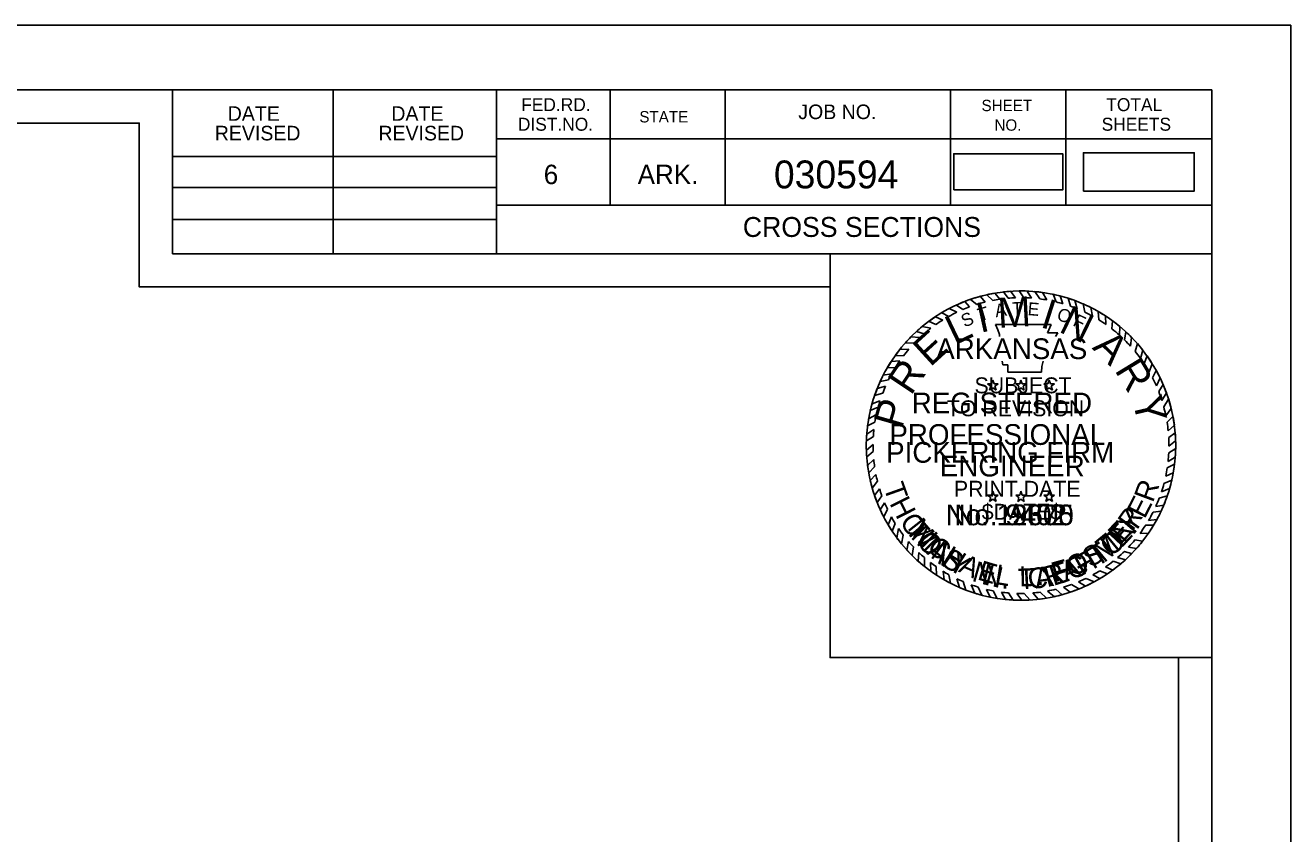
# Model space of a CAD drawing. Extents: x 1368713 to 1370673, y 380279 to 380950.
# Drawn here: x 1370239 to 1370315.2, y 380688.4 to 380737.1 of the extents above; entities that cross this region are included whole.
import ezdxf

# ---------------------------------------------------------------- set-up
doc = ezdxf.new("R2010")
doc.units = 0
for name, color, linetype in [('R_Border', 7, 'Continuous'), ('R_Border Notes', 7, 'Continuous'), ('R_No Plot', 7, 'Continuous'), ('R_Water', 7, 'Continuous'), ('STAMP_PE_CRAFTON', 7, 'Continuous'), ('STAMP_PE_FOSTER', 7, 'Continuous'), ('STAMP_PE_SEAL-INFO', 7, 'Continuous'), ('STAMP_PE_TAEGTMEYER', 7, 'Continuous'), ('STAMP_PE_TXT', 7, 'Continuous'), ('STAMP_PRELIMINARY', 7, 'Continuous')]:
    doc.layers.add(name, color=color, linetype=linetype)

msp = doc.modelspace()

# ---------------------------------------------------------------- linework, layer by layer
at = {"layer": 'R_Border'}
for p, q in [((1369994.283, 380733.214), (1370310.463, 380733.214)), ((1370247.823, 380723.334), (1370247.823, 380733.214)), ((1370257.503, 380723.334), (1370257.503, 380733.214)), ((1370267.363, 380733.214), (1370267.363, 380723.334)), ((1370274.203, 380733.214), (1370274.203, 380726.274)), ((1370281.143, 380733.214), (1370281.143, 380726.274)), ((1370294.723, 380733.214), (1370294.723, 380726.274)), ((1370301.663, 380733.214), (1370301.663, 380726.274)), ((1370310.463, 380527.754), (1370310.463, 380733.214)), ((1370310.463, 380730.274), (1370267.363, 380730.274)), ((1370310.463, 380730.294), (1370310.463, 380730.294)), ((1370247.823, 380729.194), (1370267.363, 380729.194)), ((1370247.823, 380727.334), (1370267.363, 380727.334)), ((1370310.463, 380726.274), (1370267.363, 380726.274)), ((1370270.323, 380726.274), (1370310.463, 380726.274)), ((1370247.823, 380725.394), (1370267.363, 380725.394)), ((1370310.463, 380723.334), (1370247.823, 380723.334))]:
    msp.add_line(p, q, dxfattribs=at)
at = {"layer": 'R_No Plot'}
for points in [[(1369981.875, 380737.108), (1370315.215, 380737.108), (1370315.215, 380523.771), (1369981.875, 380523.771)], [(1370308.463, 380632.484), (1369996.283, 380632.484), (1369996.283, 380731.214), (1370245.823, 380731.214), (1370245.823, 380721.334), (1370263.363, 380721.334), (1370287.463, 380721.334), (1370287.463, 380699.001), (1370308.463, 380699.001)], [(1369996.283, 380731.214), (1370245.823, 380731.214), (1370245.823, 380721.334), (1370263.363, 380721.334), (1370287.463, 380721.334), (1370287.463, 380699.001), (1370308.463, 380699.001), (1370308.463, 380529.754), (1369996.283, 380529.754)], [(1370287.463, 380723.334), (1370310.463, 380723.334), (1370310.463, 380699.001), (1370287.463, 380699.001)]]:
    msp.add_lwpolyline(points, close=True, dxfattribs=at)
at = {"layer": 'R_Water'}
for points in [[(1370302.721, 380727.118), (1370309.404, 380727.118), (1370309.404, 380729.429), (1370302.721, 380729.429)], [(1370294.911, 380727.181), (1370301.474, 380727.181), (1370301.474, 380729.367), (1370294.911, 380729.367)]]:
    msp.add_lwpolyline(points, close=True, dxfattribs=at)
at = {"layer": 'STAMP_PE_SEAL-INFO'}
for p, q in [((1370297.899, 380721.038), (1370298.18, 380720.655)), ((1370298.634, 380720.684), (1370298.322, 380721.077)), ((1370299.132, 380720.688), (1370298.854, 380721.098)), ((1370299.59, 380720.668), (1370299.332, 380721.092)), ((1370300.096, 380720.617), (1370299.804, 380721.061)), ((1370300.522, 380720.552), (1370300.264, 380721.008)), ((1370295.067, 380720.246), (1370295.456, 380719.971)), ((1370295.574, 380720.461), (1370295.869, 380720.136)), ((1370295.922, 380720.589), (1370296.303, 380720.284)), ((1370296.513, 380720.771), (1370296.801, 380720.424)), ((1370296.901, 380720.868), (1370297.257, 380720.525)), ((1370297.383, 380720.964), (1370297.682, 380720.597)), ((1370301.084, 380720.434), (1370300.91, 380720.893)), ((1370301.486, 380720.325), (1370301.326, 380720.794)), ((1370301.937, 380720.179), (1370301.796, 380720.658)), ((1370302.356, 380720.019), (1370302.211, 380720.515)), ((1370302.817, 380719.813), (1370302.714, 380720.311)), ((1370293.801, 380719.539), (1370294.243, 380719.337)), ((1370294.188, 380719.783), (1370294.62, 380719.56)), ((1370294.636, 380720.034), (1370295.099, 380719.809)), ((1370303.263, 380719.584), (1370303.176, 380720.093)), ((1370303.65, 380719.357), (1370303.611, 380719.858)), ((1370304.085, 380719.071), (1370304.054, 380719.586)), ((1370293.004, 380718.946), (1370293.533, 380718.845)), ((1370293.38, 380719.273), (1370293.836, 380719.068)), ((1370297.436, 380719.068), (1370300.78, 380719.068)), ((1370297.557, 380718.76), (1370297.436, 380719.068)), ((1370297.661, 380718.462), (1370297.557, 380718.76)), ((1370300.78, 380719.068), (1370300.555, 380718.576)), ((1370304.446, 380718.804), (1370304.48, 380719.291)), ((1370304.892, 380718.432), (1370304.912, 380718.954)), ((1370292.002, 380717.978), (1370292.523, 380717.939)), ((1370292.324, 380718.322), (1370292.869, 380718.281)), ((1370292.66, 380718.645), (1370293.119, 380718.507)), ((1370297.668, 380718.348), (1370297.661, 380718.462)), ((1370300.555, 380718.576), (1370301.187, 380718.576)), ((1370301.187, 380718.576), (1370301.042, 380718.348)), ((1370305.205, 380718.139), (1370305.274, 380718.638)), ((1370305.564, 380717.766), (1370305.63, 380718.292)), ((1370291.378, 380717.197), (1370291.883, 380717.192)), ((1370291.656, 380717.566), (1370292.205, 380717.589)), ((1370305.837, 380717.45), (1370305.974, 380717.921)), ((1370306.161, 380717.032), (1370306.297, 380717.532)), ((1370306.381, 380716.717), (1370306.559, 380717.181)), ((1370290.897, 380716.452), (1370291.386, 380716.472)), ((1370291.143, 380716.853), (1370291.659, 380716.886)), ((1370297.859, 380716.639), (1370297.833, 380716.857)), ((1370298.174, 380716.639), (1370297.859, 380716.639)), ((1370298.174, 380716.209), (1370298.174, 380716.639)), ((1370300.219, 380716.547), (1370300.203, 380716.209)), ((1370300.297, 380716.857), (1370300.219, 380716.547)), ((1370306.689, 380716.22), (1370306.872, 380716.711)), ((1370290.478, 380715.639), (1370290.981, 380715.743)), ((1370290.666, 380716.028), (1370291.164, 380716.093)), ((1370300.203, 380716.209), (1370298.174, 380716.209)), ((1370306.889, 380715.853), (1370307.115, 380716.298)), ((1370307.12, 380715.369), (1370307.346, 380715.854)), ((1370290.144, 380714.801), (1370290.628, 380714.937)), ((1370290.294, 380715.207), (1370290.798, 380715.353)), ((1370307.26, 380715.032), (1370307.524, 380715.466)), ((1370307.455, 380714.483), (1370307.726, 380714.958)), ((1370289.987, 380714.298), (1370290.465, 380714.466)), ((1370307.563, 380714.119), (1370307.857, 380714.571)), ((1370290.247, 380713.644), (1370289.782, 380713.395)), ((1370289.883, 380713.89), (1370290.353, 380714.083)), ((1370307.696, 380713.56), (1370308.015, 380714.007)), ((1370307.765, 380713.18), (1370308.118, 380713.533)), ((1370290.102, 380712.75), (1370289.666, 380712.469)), ((1370290.161, 380713.185), (1370289.716, 380712.963)), ((1370307.831, 380712.671), (1370308.204, 380713.007)), ((1370290.066, 380712.324), (1370289.645, 380712.068)), ((1370307.863, 380712.253), (1370308.254, 380712.544)), ((1370307.876, 380711.735), (1370308.281, 380712.056)), ((1370290.049, 380711.831), (1370289.644, 380711.496)), ((1370290.056, 380711.424), (1370289.665, 380711.099)), ((1370307.825, 380710.823), (1370308.259, 380711.08)), ((1370307.865, 380711.329), (1370308.284, 380711.606)), ((1370290.089, 380710.929), (1370289.718, 380710.572)), ((1370290.141, 380710.5), (1370289.787, 380710.126)), ((1370307.775, 380710.435), (1370308.218, 380710.654)), ((1370290.22, 380710.041), (1370289.88, 380709.673)), ((1370290.313, 380709.622), (1370290.001, 380709.207)), ((1370307.576, 380709.483), (1370308.048, 380709.685)), ((1370307.684, 380709.935), (1370308.139, 380710.13)), ((1370290.437, 380709.175), (1370290.142, 380708.757)), ((1370307.429, 380708.989), (1370307.919, 380709.19)), ((1370290.578, 380708.752), (1370290.296, 380708.34)), ((1370290.744, 380708.325), (1370290.483, 380707.903)), ((1370307.08, 380708.095), (1370307.568, 380708.191)), ((1370307.294, 380708.609), (1370307.777, 380708.74)), ((1370290.916, 380707.942), (1370290.688, 380707.481)), ((1370291.151, 380707.484), (1370290.96, 380706.994)), ((1370306.647, 380707.26), (1370307.148, 380707.314)), ((1370306.919, 380707.758), (1370307.407, 380707.826)), ((1370291.387, 380707.08), (1370291.203, 380706.609)), ((1370291.589, 380706.768), (1370291.479, 380706.216)), ((1370306.475, 380706.979), (1370306.953, 380706.973)), ((1370291.87, 380706.378), (1370291.768, 380705.847)), ((1370292.174, 380706), (1370292.087, 380705.48)), ((1370305.828, 380706.091), (1370306.289, 380706.012)), ((1370306.136, 380706.485), (1370306.64, 380706.488)), ((1370292.476, 380705.663), (1370292.414, 380705.14)), ((1370292.799, 380705.337), (1370292.769, 380704.808)), ((1370293.143, 380705.025), (1370293.14, 380704.496)), ((1370304.784, 380705.026), (1370305.255, 380704.897)), ((1370305.19, 380705.399), (1370305.631, 380705.261)), ((1370305.445, 380705.658), (1370305.922, 380705.573)), ((1370293.503, 380704.73), (1370293.522, 380704.206)), ((1370293.842, 380704.481), (1370293.878, 380703.962)), ((1370303.709, 380704.231), (1370304.158, 380704.036)), ((1370304.053, 380704.459), (1370304.491, 380704.27)), ((1370304.513, 380704.802), (1370304.981, 380704.656)), ((1370294.269, 380704.199), (1370294.329, 380703.686)), ((1370294.619, 380703.993), (1370294.71, 380703.48)), ((1370295.1, 380703.743), (1370295.257, 380703.222)), ((1370295.473, 380703.574), (1370295.645, 380703.064)), ((1370302.427, 380703.564), (1370302.851, 380703.303)), ((1370302.887, 380703.773), (1370303.37, 380703.561)), ((1370303.294, 380703.986), (1370303.711, 380703.754)), ((1370295.965, 380703.382), (1370296.174, 380702.88)), ((1370296.375, 380703.247), (1370296.601, 380702.758)), ((1370296.883, 380703.109), (1370297.095, 380702.643)), ((1370297.28, 380703.023), (1370297.527, 380702.565)), ((1370297.78, 380702.941), (1370298.02, 380702.501)), ((1370298.217, 380702.894), (1370298.491, 380702.465)), ((1370298.702, 380702.867), (1370299.004, 380702.454)), ((1370299.161, 380702.865), (1370299.505, 380702.469)), ((1370299.68, 380702.892), (1370300.006, 380702.512)), ((1370300.118, 380702.938), (1370300.491, 380702.58)), ((1370300.563, 380703.008), (1370300.952, 380702.668)), ((1370301.056, 380703.112), (1370301.434, 380702.787)), ((1370301.515, 380703.236), (1370301.932, 380702.939)), ((1370302.008, 380703.399), (1370302.451, 380703.131))]:
    msp.add_line(p, q, dxfattribs=at)
for radius, start, end in [(9.323, 93.93815, 96.55172), (9.323, 87.72979, 90.67067), (9.323, 81.97315, 84.82355), (9.323, 111.31242, 114.70259), (9.323, 105.23389, 109.03519), (8.914, 104.03521, 107.36155), (9.323, 99.75254, 102.77648), (8.914, 98.25799, 101.03289), (8.914, 92.11016, 95.03666), (8.914, 85.96279, 88.9097), (8.914, 79.92642, 82.69597), (9.323, 75.31251, 77.94263), (8.914, 73.55748, 76.23144), (9.323, 69.60611, 72.30577), (9.323, 63.13288, 66.2704), (9.323, 123.61993, 126.59063), (9.323, 117.65441, 120.80988), (8.914, 115.68692, 119.15827), (8.914, 110.30864, 113.16588), (8.914, 67.62483, 70.50398), (8.914, 61.15575, 64.37837), (9.323, 56.90029, 60.09423), (9.323, 129.73259, 132.53764), (8.914, 127.52969, 130.96829), (8.914, 121.97456, 125.11001), (8.914, 54.92383, 58.27016), (8.914, 48.30163, 52.03953), (9.323, 50.3492, 53.71593), (9.323, 135.40208, 138.30314), (8.914, 133.13306, 136.25623), (8.914, 42.22116, 45.55119), (9.323, 44.3405, 47.39292), (9.323, 141.60556, 144.44865), (8.914, 139.30101, 142.58729), (8.914, 36.13503, 39.53106), (9.323, 38.12472, 41.23157), (9.323, 31.96138, 35.42937), (9.323, 147.00719, 149.89904), (8.914, 145.01972, 148.21036), (8.914, 29.90321, 33.66454), (9.323, 152.86398, 155.51889), (8.914, 151.03153, 153.57304), (8.914, 23.77322, 27.22114), (9.323, 25.93909, 29.01247), (9.323, 158.40766, 161.07015), (8.914, 156.34018, 159.23194), (8.914, 17.68022, 21.42509), (9.323, 19.95381, 23.31409), (9.323, 164.3068, 166.89395), (8.914, 162.43309, 165.00133), (9.323, 13.84205, 17.44468), (9.323, 170.0003, 172.68778), (8.914, 167.90481, 170.90393), (8.914, 11.54445, 15.23639), (9.323, 7.58519, 10.86211), (8.914, 173.73, 176.47337), (8.914, 5.7599, 9.06056), (9.323, 175.74093, 178.2066), (8.914, 359.73289, 3.06392), (9.323, 1.72155, 4.72681), (9.323, 181.72508, 184.16255), (8.914, 179.64537, 182.26333), (8.914, 353.86319, 357.12742), (9.323, 355.71562, 358.95694), (9.323, 187.42037, 190.19271), (8.914, 185.45389, 188.23401), (8.914, 348.07782, 351.34355), (9.323, 349.83047, 353.08845), (9.323, 193.03695, 195.99732), (8.914, 191.22736, 193.98583), (9.323, 343.89247, 347.03502), (8.914, 196.96751, 199.83526), (8.914, 341.77699, 345.09248), (9.323, 198.89671, 201.62812), (8.914, 202.77613, 205.47915), (8.914, 335.6038, 339.18578), (9.323, 337.38367, 340.99332), (9.323, 204.54793, 207.43282), (8.914, 208.78826, 211.79343), (8.914, 329.55488, 333.20757), (9.323, 331.40371, 334.93315), (9.323, 210.86355, 213.65709), (8.914, 214.18375, 217.27474), (8.914, 323.58513, 327.44069), (9.323, 325.44052, 328.98725), (9.323, 216.61154, 219.49098), (8.914, 220.39088, 223.30564), (8.914, 316.65308, 320.37109), (9.323, 318.28455, 321.80429), (9.323, 222.47995, 225.38008), (8.914, 226.24938, 229.24068), (8.914, 310.77436, 314.31605), (9.323, 312.45177, 315.66328), (9.323, 228.36648, 231.34802), (8.914, 232.22904, 234.93361), (8.914, 299.07679, 302.17235), (8.914, 304.82299, 308.51428), (9.323, 306.37206, 310.20799), (9.323, 234.29502, 236.94517), (8.914, 238.22227, 240.83529), (9.323, 240.1977, 242.86128), (8.914, 244.32043, 246.94859), (8.914, 292.87452, 296.11851), (9.323, 294.64808, 298.21662), (9.323, 300.62101, 303.87026), (9.323, 246.57598, 249.15579), (8.914, 250.34912, 253.12157), (9.323, 252.59667, 255.32518), (8.914, 256.50505, 259.11916), (8.914, 262.37828, 265.20115), (8.914, 268.3215, 271.27698), (8.914, 274.61565, 277.44863), (8.914, 280.34588, 283.58137), (9.323, 282.31994, 285.37019), (8.914, 286.64233, 289.97826), (9.323, 288.57086, 291.97334), (9.323, 258.44328, 261.13983), (9.323, 264.19784, 267.10092), (9.323, 270.25484, 273.33609), (9.323, 276.42389, 279.43574)]:
    msp.add_arc((1370298.963, 380711.776), radius, start, end, dxfattribs=at)
at = {"layer": 'STAMP_PE_TXT'}
for p, q in [((1370297.189, 380715.492), (1370297.265, 380715.725)), ((1370297.265, 380715.725), (1370297.34, 380715.492)), ((1370298.887, 380715.492), (1370298.963, 380715.725)), ((1370298.963, 380715.725), (1370299.038, 380715.492)), ((1370300.585, 380715.492), (1370300.661, 380715.725)), ((1370300.661, 380715.725), (1370300.736, 380715.492)), ((1370297.142, 380715.348), (1370296.944, 380715.492)), ((1370296.944, 380715.492), (1370297.189, 380715.492)), ((1370297.066, 380715.114), (1370297.142, 380715.348)), ((1370297.265, 380715.259), (1370297.066, 380715.114)), ((1370297.463, 380715.114), (1370297.265, 380715.259)), ((1370297.34, 380715.492), (1370297.586, 380715.492)), ((1370297.586, 380715.492), (1370297.387, 380715.348)), ((1370297.387, 380715.348), (1370297.463, 380715.114)), ((1370298.84, 380715.348), (1370298.642, 380715.492)), ((1370298.642, 380715.492), (1370298.887, 380715.492)), ((1370298.764, 380715.114), (1370298.84, 380715.348)), ((1370298.963, 380715.259), (1370298.764, 380715.114)), ((1370299.161, 380715.114), (1370298.963, 380715.259)), ((1370299.038, 380715.492), (1370299.284, 380715.492)), ((1370299.284, 380715.492), (1370299.085, 380715.348)), ((1370299.085, 380715.348), (1370299.161, 380715.114)), ((1370300.538, 380715.348), (1370300.34, 380715.492)), ((1370300.34, 380715.492), (1370300.585, 380715.492)), ((1370300.462, 380715.114), (1370300.538, 380715.348)), ((1370300.661, 380715.259), (1370300.462, 380715.114)), ((1370300.859, 380715.114), (1370300.661, 380715.259)), ((1370300.736, 380715.492), (1370300.982, 380715.492)), ((1370300.982, 380715.492), (1370300.783, 380715.348)), ((1370300.783, 380715.348), (1370300.859, 380715.114)), ((1370297.142, 380708.641), (1370296.944, 380708.785)), ((1370296.944, 380708.785), (1370297.189, 380708.785)), ((1370297.189, 380708.785), (1370297.265, 380709.018)), ((1370297.265, 380709.018), (1370297.34, 380708.785)), ((1370297.34, 380708.785), (1370297.586, 380708.785)), ((1370297.586, 380708.785), (1370297.387, 380708.641)), ((1370298.84, 380708.641), (1370298.642, 380708.785)), ((1370298.642, 380708.785), (1370298.887, 380708.785)), ((1370298.887, 380708.785), (1370298.963, 380709.018)), ((1370298.963, 380709.018), (1370299.038, 380708.785)), ((1370299.038, 380708.785), (1370299.284, 380708.785)), ((1370299.284, 380708.785), (1370299.085, 380708.641)), ((1370300.538, 380708.641), (1370300.34, 380708.785)), ((1370300.34, 380708.785), (1370300.585, 380708.785)), ((1370300.585, 380708.785), (1370300.661, 380709.018)), ((1370300.661, 380709.018), (1370300.736, 380708.785)), ((1370300.736, 380708.785), (1370300.982, 380708.785)), ((1370300.982, 380708.785), (1370300.783, 380708.641)), ((1370297.066, 380708.407), (1370297.142, 380708.641)), ((1370297.265, 380708.552), (1370297.066, 380708.407)), ((1370297.463, 380708.407), (1370297.265, 380708.552)), ((1370297.387, 380708.641), (1370297.463, 380708.407)), ((1370298.764, 380708.407), (1370298.84, 380708.641)), ((1370298.963, 380708.552), (1370298.764, 380708.407)), ((1370299.161, 380708.407), (1370298.963, 380708.552)), ((1370299.085, 380708.641), (1370299.161, 380708.407)), ((1370300.462, 380708.407), (1370300.538, 380708.641)), ((1370300.661, 380708.552), (1370300.462, 380708.407)), ((1370300.859, 380708.407), (1370300.661, 380708.552)), ((1370300.783, 380708.641), (1370300.859, 380708.407))]:
    msp.add_line(p, q, dxfattribs=at)
at = {"layer": 'STAMP_PRELIMINARY'}
msp.add_circle((1370298.963, 380711.776), 9.323, dxfattribs=at)

# ---------------------------------------------------------------- texts
at = {"layer": 'R_Border'}
for s, height, p in [('FED.RD.', 0.7819, (1370268.843, 380731.934)), ('SHEET', 0.684, (1370296.583, 380731.934)), ('TOTAL', 0.7819, (1370304.103, 380731.934)), ('DATE', 0.8792, (1370251.16, 380731.35)), ('DATE', 0.8792, (1370261.02, 380731.35)), ('STATE', 0.684, (1370275.963, 380731.254)), ('JOB NO.', 0.8792, (1370285.543, 380731.454)), ('REVISED', 0.8792, (1370250.38, 380730.17)), ('REVISED', 0.8792, (1370260.24, 380730.17)), ('DIST.NO.', 0.7819, (1370268.643, 380730.754)), ('NO.', 0.684, (1370297.363, 380730.754)), ('SHEETS', 0.7819, (1370303.823, 380730.754)), ('6', 1.172, (1370270.203, 380727.534)), ('ARK.', 1.1723, (1370275.863, 380727.534))]:
    msp.add_text(s, height=height, rotation=360, dxfattribs=at).set_placement(p)
at = {"layer": 'R_Border Notes'}
for s, height, p in [('030594', 1.68, (1370284.074, 380727.279)), ('CROSS SECTIONS', 1.2, (1370282.201, 380724.352))]:
    msp.add_text(s, height=height, rotation=360, dxfattribs=at).set_placement(p)
at = {"layer": 'STAMP_PE_CRAFTON'}
for s, rotation, p in [('No. 12370', 360, (1370294.425, 380706.973)), ('T', 310.74416, (1370291.929, 380706.674)), ('N', 49.24107, (1370305.245, 380705.798)), ('O', 317.64216, (1370292.596, 380705.863)), ('O', 41.83906, (1370304.398, 380705.017)), ('N', 324.45371, (1370293.442, 380705.078)), ('T', 34.11362, (1370303.539, 380704.415)), ('Y', 331.16864, (1370294.475, 380704.362)), ('F', 28.78207, (1370302.624, 380703.906)), ('N', 347.47515, (1370296.529, 380703.446)), ('C', 6.01169, (1370299.434, 380703.117)), ('R', 14.81888, (1370300.53, 380703.232)), ('A', 20.51248, (1370301.643, 380703.532)), ('.', 356.89262, (1370297.759, 380703.169))]:
    msp.add_text(s, height=1.25, rotation=rotation, dxfattribs=at).set_placement(p)
at = {"layer": 'STAMP_PE_FOSTER'}
for s, height, rotation, p in [('No. 9402', 1.25, 360, (1370294.948, 380706.973)), ('R', 1.2, 54.5031, (1370305.687, 380706.587)), ('M', 1.2, 308.33902, (1370292.079, 380706.798)), ('E', 1.2, 46.96131, (1370304.963, 380705.766)), ('I', 1.2, 314.18423, (1370292.876, 380705.861)), ('T', 1.2, 39.41938, (1370304.105, 380705.016)), ('C', 1.2, 319.87327, (1370293.23, 380705.507)), ('S', 1.2, 31.72336, (1370303.153, 380704.389)), ('H', 1.2, 327.72349, (1370294.16, 380704.771)), ('A', 1.2, 335.72761, (1370295.14, 380704.189)), ('O', 1.2, 23.71897, (1370302.042, 380703.859)), ('E', 1.2, 343.5779, (1370296.278, 380703.719)), ('L', 1.2, 350.81148, (1370297.337, 380703.441)), ('L', 1.2, 1.26658, (1370298.876, 380703.285)), ('F', 1.2, 15.86908, (1370300.998, 380703.531)), ('.', 1.2, 6.80354, (1370299.923, 380703.343))]:
    msp.add_text(s, height=height, rotation=rotation, dxfattribs=at).set_placement(p)
at = {"layer": 'STAMP_PE_TAEGTMEYER'}
for s, rotation, p in [('T', 289.64597, (1370290.657, 380709.286)), ('R', 69.57001, (1370306.908, 380708.291)), ('H', 296.73386, (1370291.017, 380708.302)), ('No. 19605', 360, (1370294.425, 380706.973)), ('E', 63.0984, (1370306.409, 380707.309)), ('O', 303.77078, (1370291.61, 380707.194)), ('Y', 53.99864, (1370305.74, 380706.369)), ('M', 314.20329, (1370292.265, 380706.243)), ('E', 46.80938, (1370305.001, 380705.554)), ('A', 321.0594, (1370293.226, 380705.278)), ('M', 39.30005, (1370303.961, 380704.674)), ('S', 327.82385, (1370294.053, 380704.634)), ('G', 23.30524, (1370301.962, 380703.638)), ('T', 31.46601, (1370303.063, 380704.131)), ('N', 344.27273, (1370295.949, 380703.628)), ('T', 3.00609, (1370298.827, 380703.097)), ('A', 8.98261, (1370299.874, 380703.152)), ('E', 17.68363, (1370300.913, 380703.308)), ('.', 350.64643, (1370297.162, 380703.296))]:
    msp.add_text(s, height=1.25, rotation=rotation, dxfattribs=at).set_placement(p)
at = {"layer": 'STAMP_PE_TXT'}
for s, height, rotation, p in [('A', 0.781, 9.0679, (1370297.447, 380719.505)), ('T', 0.781, 1.82479, (1370298.433, 380719.634)), ('E', 0.781, 355.20019, (1370299.343, 380719.643)), ('S', 0.781, 23.5541, (1370295.561, 380718.88)), ('T', 0.781, 16.311, (1370296.484, 380719.252)), ('O', 0.781, 342.25065, (1370301.07, 380719.366)), ('F', 0.781, 335.00755, (1370302.035, 380719.028)), ('ARKANSAS', 1.25, 360, (1370293.855, 380716.987)), ('REGISTERED', 1.25, 360, (1370292.379, 380713.717)), ('PROFESSIONAL', 1.25, 360, (1370291.031, 380711.816)), ('ENGINEER', 1.25, 360, (1370294.072, 380709.914))]:
    msp.add_text(s, height=height, rotation=rotation, dxfattribs=at).set_placement(p)
at = {"layer": 'STAMP_PRELIMINARY'}
for s, height, rotation, p in [('I', 1.8, 12.52485, (1370296.5, 380718.563)), ('M', 1.8, 3.10738, (1370297.598, 380718.872)), ('I', 1.8, 342.31637, (1370300.066, 380718.939)), ('L', 1.8, 25.51305, (1370294.971, 380717.804)), ('N', 1.8, 333.9382, (1370301.174, 380718.665)), ('E', 1.8, 42.35784, (1370293.489, 380716.473)), ('A', 1.8, 315.65789, (1370303.207, 380717.64)), ('R', 1.8, 56.22922, (1370292.333, 380714.74)), ('R', 1.8, 301.38306, (1370304.575, 380716.326)), ('SUBJECT', 0.96, 360, (1370296.163, 380714.926)), ('Y', 1.8, 283.25926, (1370305.665, 380714.539)), ('P', 1.8, 73.91301, (1370291.784, 380712.717)), ('TO REVISION', 0.96, 360, (1370294.498, 380713.541)), ('PICKERING FIRM', 1.25, 360, (1370290.836, 380710.739)), ('PRINT DATE', 0.96, 360, (1370294.92, 380708.692)), ('$DATE$', 0.96, 360, (1370296.597, 380707.307))]:
    msp.add_text(s, height=height, rotation=rotation, dxfattribs=at).set_placement(p)

doc.saveas('drawing.dxf')
